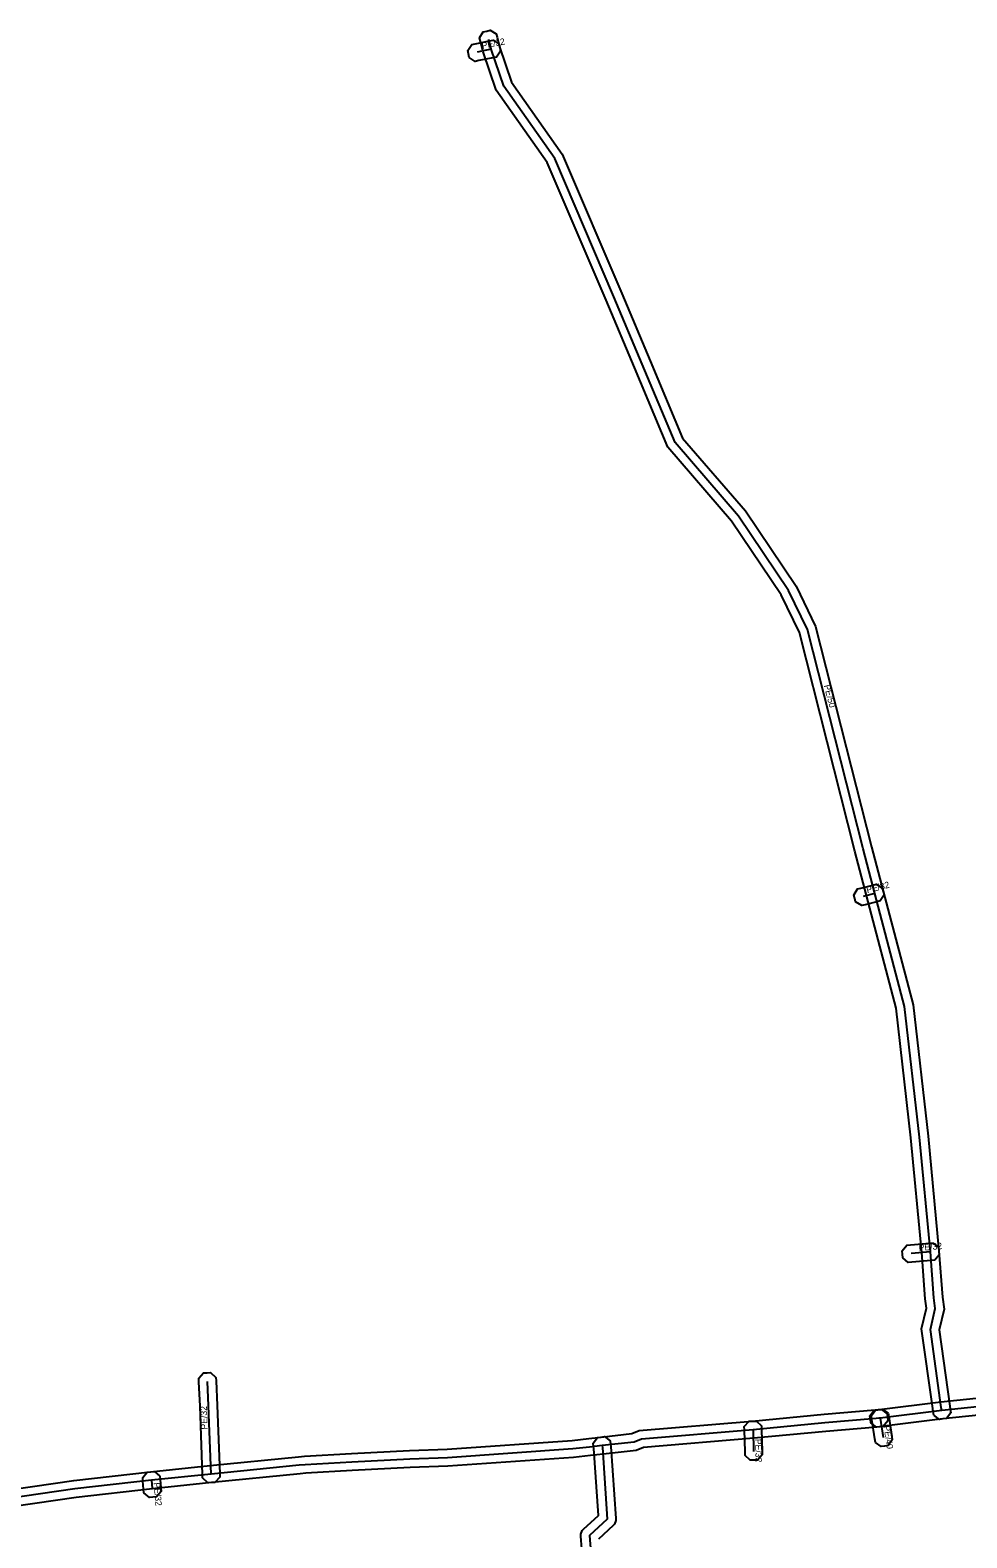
# Model space of a CAD drawing. Extents: x -682697 to -681888, y -1059966 to -1059631.
# Drawn here: x -682290.2 to -682181.2, y -1059806.3 to -1059630.8 of the extents above; entities that cross this region are included whole.
import ezdxf

# ---------------------------------------------------------------- set-up
doc = ezdxf.new("R2010")
doc.units = 0
for name, color, linetype in [('1', 7, 'Continuous'), ('24', 7, 'Continuous'), ('30', 7, 'Continuous')]:
    doc.layers.add(name, color=color, linetype=linetype)

msp = doc.modelspace()

# ---------------------------------------------------------------- linework, layer by layer
at = {"layer": '1'}
for points in [[(-682185.05, -1059792.05), (-682185.11, -1059791.64), (-682185.16, -1059791.29), (-682186.46, -1059782.02), (-682185.89, -1059779.6), (-682186.03, -1059778.5), (-682186.44, -1059773.12), (-682187.7, -1059759.78), (-682189.43, -1059744.65), (-682192.88, -1059731.56), (-682194.24, -1059726.37), (-682200.69, -1059700.92), (-682202.81, -1059696.54), (-682208.58, -1059687.97), (-682216.02, -1059679.34), (-682219.9, -1059670.08), (-682223.2, -1059662.24), (-682230.05, -1059646.21), (-682236, -1059637.78), (-682237.52, -1059633.3), (-682237.82, -1059632.1), (-682237.92, -1059631.7), (-682237.49, -1059630.99), (-682237.09, -1059630.89), (-682236.69, -1059630.79), (-682235.98, -1059631.22), (-682235.88, -1059631.62), (-682235.6, -1059632.74), (-682234.2, -1059636.86), (-682228.29, -1059645.23), (-682221.36, -1059661.46), (-682218.06, -1059669.3), (-682214.3, -1059678.28), (-682206.98, -1059686.75), (-682201.07, -1059695.54), (-682198.81, -1059700.24), (-682192.3, -1059725.87), (-682190.94, -1059731.06), (-682187.45, -1059744.27), (-682185.7, -1059759.58), (-682184.44, -1059772.96), (-682184.04, -1059778.3), (-682183.85, -1059779.7), (-682184.42, -1059782.12), (-682183.18, -1059791.01), (-682183.13, -1059791.36), (-682183.07, -1059791.77), (-682183.57, -1059792.43), (-682183.98, -1059792.49), (-682184.39, -1059792.55)], [(-682235.95, -1059633.92), (-682236.36, -1059634), (-682238.02, -1059634.34), (-682238.43, -1059634.42), (-682239.12, -1059633.97), (-682239.2, -1059633.56), (-682239.28, -1059633.16), (-682238.83, -1059632.46), (-682238.42, -1059632.38), (-682236.76, -1059632.04), (-682236.35, -1059631.96), (-682235.66, -1059632.41), (-682235.58, -1059632.82), (-682235.5, -1059633.23)], [(-682191.27, -1059732.18), (-682191.67, -1059732.28), (-682193.04, -1059732.62), (-682193.44, -1059732.72), (-682194.15, -1059732.29), (-682194.25, -1059731.89), (-682194.35, -1059731.49), (-682193.92, -1059730.78), (-682193.52, -1059730.68), (-682192.15, -1059730.34), (-682191.75, -1059730.24), (-682191.04, -1059730.67), (-682190.94, -1059731.07), (-682190.84, -1059731.47)], [(-682184.94, -1059774), (-682185.36, -1059774.04), (-682187.61, -1059774.23), (-682188.02, -1059774.26), (-682188.65, -1059773.73), (-682188.69, -1059773.31), (-682188.72, -1059772.9), (-682188.19, -1059772.27), (-682187.77, -1059772.23), (-682185.52, -1059772.04), (-682185.11, -1059772.01), (-682184.48, -1059772.54), (-682184.44, -1059772.96), (-682184.41, -1059773.37)], [(-682270.16, -1059799.36), (-682270.18, -1059798.95), (-682270.47, -1059791.01), (-682270.6, -1059788.17), (-682270.62, -1059787.75), (-682270.06, -1059787.14), (-682269.65, -1059787.12), (-682269.23, -1059787.1), (-682268.62, -1059787.66), (-682268.6, -1059788.07), (-682268.47, -1059790.93), (-682268.18, -1059798.87), (-682268.17, -1059799.29), (-682268.73, -1059799.89), (-682269.14, -1059799.91), (-682269.56, -1059799.92)], [(-682190.34, -1059791.83), (-682190.28, -1059792.24), (-682189.93, -1059794.52), (-682189.87, -1059794.93), (-682190.36, -1059795.59), (-682190.77, -1059795.66), (-682191.18, -1059795.72), (-682191.84, -1059795.23), (-682191.91, -1059794.82), (-682192.26, -1059792.54), (-682192.32, -1059792.13), (-682191.83, -1059791.47), (-682191.42, -1059791.4), (-682191.01, -1059791.34)], [(-682205.1, -1059793.31), (-682205.09, -1059793.72), (-682205.02, -1059796.27), (-682205.01, -1059796.69), (-682205.58, -1059797.29), (-682205.99, -1059797.3), (-682206.41, -1059797.31), (-682207.01, -1059796.74), (-682207.02, -1059796.33), (-682207.09, -1059793.78), (-682207.1, -1059793.36), (-682206.53, -1059792.76), (-682206.12, -1059792.75), (-682205.7, -1059792.74)], [(-682275.15, -1059799.14), (-682275.11, -1059799.56), (-682275.03, -1059800.52), (-682275, -1059800.93), (-682275.53, -1059801.56), (-682275.95, -1059801.6), (-682276.36, -1059801.63), (-682276.99, -1059801.1), (-682277.03, -1059800.68), (-682277.11, -1059799.72), (-682277.14, -1059799.31), (-682276.61, -1059798.68), (-682276.19, -1059798.64), (-682275.78, -1059798.61)]]:
    msp.add_lwpolyline(points, close=True, dxfattribs=at)
for points in [[(-682146.97, -1059788.66), (-682184.01, -1059792.49), (-682191.15, -1059793.38), (-682191.32, -1059793.4), (-682191.73, -1059793.45), (-682192.39, -1059792.94), (-682192.43, -1059792.53), (-682192.48, -1059792.12), (-682191.97, -1059791.47), (-682191.56, -1059791.42), (-682191.39, -1059791.4), (-682184.23, -1059790.51), (-682148.03, -1059786.75)], [(-682295.08, -1059801.09), (-682285.16, -1059799.65), (-682276.22, -1059798.65), (-682269.28, -1059797.92), (-682259.01, -1059796.9), (-682258.31, -1059796.82), (-682252.84, -1059796.51), (-682246.09, -1059796.16), (-682241.71, -1059796.01), (-682227.15, -1059794.99), (-682225.22, -1059794.77), (-682223.77, -1059794.6), (-682220.18, -1059794.2), (-682219.33, -1059793.85), (-682206.18, -1059792.75), (-682197.8, -1059791.95), (-682191.85, -1059791.44), (-682191.53, -1059791.41), (-682191.12, -1059791.38), (-682190.48, -1059791.9), (-682190.44, -1059792.32), (-682190.41, -1059792.73), (-682190.93, -1059793.37), (-682191.35, -1059793.41), (-682191.67, -1059793.44), (-682197.62, -1059793.95), (-682206, -1059794.75), (-682218.85, -1059795.81), (-682219.68, -1059796.16), (-682223.55, -1059796.58), (-682224.99, -1059796.75), (-682226.97, -1059796.99), (-682241.61, -1059798.01), (-682246.01, -1059798.16), (-682252.74, -1059798.51), (-682258.15, -1059798.82), (-682258.81, -1059798.89), (-682269.08, -1059799.91), (-682276, -1059800.63), (-682284.9, -1059801.63), (-682294.82, -1059803.07)], [(-682224.39, -1059828.28), (-682226.13, -1059806.15), (-682226.15, -1059805.92), (-682225.98, -1059805.49), (-682225.81, -1059805.33), (-682224.09, -1059803.75), (-682224.63, -1059795.92), (-682224.65, -1059795.72), (-682224.7, -1059795.31), (-682224.2, -1059794.65), (-682223.79, -1059794.6), (-682223.38, -1059794.54), (-682222.72, -1059795.05), (-682222.67, -1059795.46), (-682222.63, -1059795.72), (-682222.06, -1059804.09), (-682222.05, -1059804.32), (-682222.21, -1059804.74), (-682222.38, -1059804.9), (-682224.09, -1059806.48)]]:
    msp.add_lwpolyline(points, dxfattribs=at)
at = {"layer": '24'}
for points in [[(-682184.12, -1059791.5), (-682184.17, -1059791.15), (-682185.44, -1059782.07), (-682184.87, -1059779.65), (-682185.03, -1059778.4), (-682185.44, -1059773.04), (-682186.7, -1059759.68), (-682188.44, -1059744.46), (-682191.91, -1059731.31), (-682193.27, -1059726.12), (-682199.75, -1059700.58), (-682201.94, -1059696.04), (-682207.78, -1059687.36), (-682215.16, -1059678.81), (-682218.98, -1059669.69), (-682222.28, -1059661.85), (-682229.17, -1059645.72), (-682235.1, -1059637.32), (-682236.56, -1059633.02), (-682236.85, -1059631.86)], [(-682236.56, -1059633.02), (-682238.22, -1059633.36)], [(-682191.91, -1059731.31), (-682193.28, -1059731.65)], [(-682185.44, -1059773.04), (-682187.69, -1059773.23)], [(-682100.2, -1059779.12), (-682112.31, -1059781.09), (-682121.02, -1059782.36), (-682123.16, -1059782.82), (-682133.42, -1059784.11), (-682135.7, -1059784.41), (-682145.18, -1059785.59), (-682146.99, -1059785.78), (-682147.07, -1059787.66), (-682184.12, -1059791.5), (-682191.27, -1059792.39), (-682191.44, -1059792.41)], [(-682269.18, -1059798.91), (-682269.47, -1059790.97), (-682269.6, -1059788.12)], [(-682191.44, -1059792.41), (-682191.76, -1059792.44), (-682197.71, -1059792.95), (-682206.09, -1059793.75), (-682219.09, -1059794.83), (-682219.93, -1059795.18), (-682223.66, -1059795.59), (-682225.11, -1059795.76), (-682227.06, -1059795.99), (-682241.66, -1059797.01), (-682246.05, -1059797.16), (-682252.79, -1059797.51), (-682258.23, -1059797.82), (-682258.91, -1059797.89), (-682269.18, -1059798.91), (-682276.11, -1059799.64), (-682285.03, -1059800.64), (-682294.95, -1059802.08)], [(-682191.27, -1059792.39), (-682190.92, -1059794.67)], [(-682206.09, -1059793.75), (-682206.02, -1059796.3)], [(-682223.66, -1059795.59), (-682223.63, -1059795.82), (-682223.06, -1059804.16), (-682225.13, -1059806.07), (-682223.39, -1059828.21), (-682222.79, -1059837.44), (-682222.07, -1059848.29), (-682222.22, -1059849.92), (-682222.15, -1059851.2)], [(-682276.11, -1059799.64), (-682276.03, -1059800.6)]]:
    msp.add_lwpolyline(points, dxfattribs=at)

# ---------------------------------------------------------------- texts
at = {"layer": '30'}
for s, rotation, p in [('PE/32', 11.5752, (-682237.59, -1059632.99)), ('PE/50', 284.2367, (-682197.85, -1059707.09)), ('PE/32', 13.9378, (-682192.79, -1059731.28)), ('PE/32', 4.8269, (-682186.77, -1059772.94)), ('PE/32', 92.0917, (-682269.58, -1059793.71)), ('PE/40', 278.7273, (-682190.9, -1059793.33)), ('PE/32', 271.5724, (-682205.86, -1059794.82)), ('PE/32', 274.7636, (-682275.87, -1059799.92))]:
    msp.add_text(s, height=0.75, rotation=rotation, dxfattribs=at).set_placement(p)

doc.saveas('drawing.dxf')
